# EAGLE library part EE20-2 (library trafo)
TRANSFORMER 1 primary winding, 2 secondary windings ERA
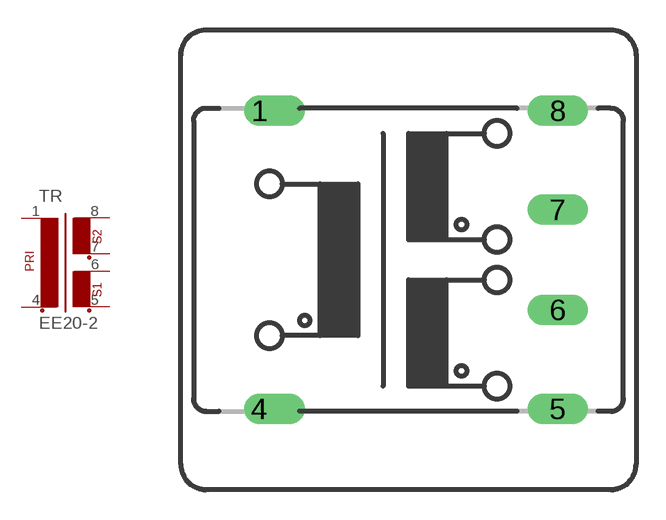
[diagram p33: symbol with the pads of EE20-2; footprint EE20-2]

Designator prefix TR

## EE20-2  [EE20-2]
1  1  pas
4  2  pas
5  3  pas
6  4  pas
7  5  pas
8  6  pas

## Footprint EE20-2 (pad centres in mm)
TRANSFORMER 1 primary winding, 2 secondary windings
drill 1.016 offset: 1 -7.493,7.493; 4 -7.493,-7.493
drill 1.016 long: 5 7.493,-7.493; 6 7.493,-2.515; 7 7.493,2.515; 8 7.493,7.493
